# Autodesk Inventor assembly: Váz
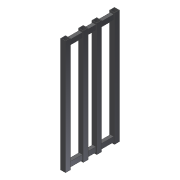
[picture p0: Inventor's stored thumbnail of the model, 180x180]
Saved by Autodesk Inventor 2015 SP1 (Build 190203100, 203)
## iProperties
Created: 2013-02
Part Number: Váz
Document SubType Name: Assembly
Designer: Marci
Author: Marci
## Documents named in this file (4)
- C:\Users\TREINA11\Desktop\#01- Polymechanics and Automation\01 - 3D Models\Pneumatic System\Váz.iam
- C:\Users\TREINA11\Desktop\#01- Polymechanics and Automation\01 - 3D Models\Pneumatic System\Vázelem.ipt
- C:\Users\TREINA11\Desktop\#01- Polymechanics and Automation\01 - 3D Models\Pneumatic System\Vázelem 53.ipt
- C:\Users\TREINA11\Desktop\#01- Polymechanics and Automation\01 - 3D Models\Pneumatic System\Vázelem 81.ipt
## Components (10 placed, 3 different names)
1. Vázelem:1 — Flush:1, Flush:2, Mate:1, Mate:4, Flush:7, Flush:8, Mate:9, Flush:17, Flush:18, Symmetry:2
2. Vázelem:2 — Flush:1, Flush:2, Mate:1, Flush:3, Flush:4, Mate:2, Mate:5, Flush:9, Flush:10, Mate:8, Flush:15, Flush:16
3. Vázelem:3 — Flush:3, Flush:4, Mate:2, Flush:5, Flush:6, Mate:3, Mate:6, Flush:11, Flush:12, Mate:7, Flush:13
4. Vázelem:4 — Flush:5, Flush:6, Mate:3, Flush:14, Symmetry:2
5. Vázelem 53:1 — Mate:5, Flush:9, Flush:10
6. Vázelem 81:1 — Mate:4, Flush:7, Flush:8
7. Vázelem 81:2 — Mate:6, Flush:11, Flush:12, Symmetry:1
8. Vázelem 81:3 — Mate:7, Flush:13, Flush:14, Symmetry:1
9. Vázelem 81:4 — Mate:9, Flush:17, Flush:18
10. Vázelem 53:2 — Mate:8, Flush:15, Flush:16
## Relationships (29: Flush 18, Mate 9, Symmetry 2)
- Flush:1: Vázelem:1 ↔ Vázelem:2
- Flush:2: Vázelem:1 ↔ Vázelem:2
- Mate:1: Vázelem:1 ↔ Vázelem:2
- Flush:3: Vázelem:2 ↔ Vázelem:3
- Flush:4: Vázelem:2 ↔ Vázelem:3
- Mate:2: Vázelem:2 ↔ Vázelem:3
- Flush:5: Vázelem:3 ↔ Vázelem:4
- Flush:6: Vázelem:3 ↔ Vázelem:4
- Mate:3: Vázelem:3 ↔ Vázelem:4
- Mate:4: Vázelem:1 ↔ Vázelem 81:1
- Flush:7: Vázelem:1 ↔ Vázelem 81:1
- Flush:8: Vázelem:1 ↔ Vázelem 81:1
- Mate:5: Vázelem:2 ↔ Vázelem 53:1
- Flush:9: Vázelem:2 ↔ Vázelem 53:1
- Flush:10: Vázelem:2 ↔ Vázelem 53:1
- Mate:6: Vázelem:3 ↔ Vázelem 81:2
- Flush:11: Vázelem:3 ↔ Vázelem 81:2
- Flush:12: Vázelem:3 ↔ Vázelem 81:2
- Mate:7: Vázelem:3 ↔ Vázelem 81:3
- Flush:13: Vázelem:3 ↔ Vázelem 81:3
- Flush:14: Vázelem:4 ↔ Vázelem 81:3
- Mate:8: Vázelem:2 ↔ Vázelem 53:2
- Flush:15: Vázelem:2 ↔ Vázelem 53:2
- Flush:16: Vázelem:2 ↔ Vázelem 53:2
- Mate:9: Vázelem:1 ↔ Vázelem 81:4
- Flush:17: Vázelem:1 ↔ Vázelem 81:4
- Flush:18: Vázelem:1 ↔ Vázelem 81:4
- Symmetry:1: Vázelem 81:2 ↔ Vázelem 81:3
- Symmetry:2: Vázelem:1 ↔ Vázelem:4
